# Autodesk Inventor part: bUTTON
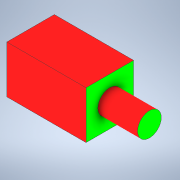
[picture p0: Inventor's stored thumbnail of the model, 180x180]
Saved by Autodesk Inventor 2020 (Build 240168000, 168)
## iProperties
Created: 2020-03
Part Number: bUTTON
Material: Generic
Document SubType Name: Modeling
Designer: Darugar
Density: 1 g/cm^3
Appearance: Default
Author: Darugar
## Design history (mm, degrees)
sketch "Sketch1"
  geometry: L1 (0, 0)-(6, 0); L2 (6, 0)-(6, -6); L3 (6, -6)-(0, -6); L4 (0, -6)-(0, 0)
  constraints: 8 end point, 2 parallel, 1 horizontal, 1 perpendicular
  dimensions: "d0" = 6 distance of L2.end L3.end; "d1" = 6 distance of L1.end L2.end
extrude "Extrusion1" new body sketch "Sketch1" distance "d2" = 10; taper "d3" = 0 deg
sketch "Sketch2"
  geometry: L1 (6, 6)-(0, 6) reference; L2 (6, 0)-(6, 6) reference; L3 (0, 6)-(6, 0); L4 (0, 6)-(0, 0) reference; L5 (0, 0)-(6, 6); C1 r 1.5 at (3, 3)
  constraints: 4 end point, 1 centre point, 1 midpoint, 1 point on line
  dimensions: "d4" = 3 diameter of C1
extrude "Extrusion2" join sketch "Sketch2" distance "d5" = 5; taper "d6" = 0 deg
body "Solid1"
